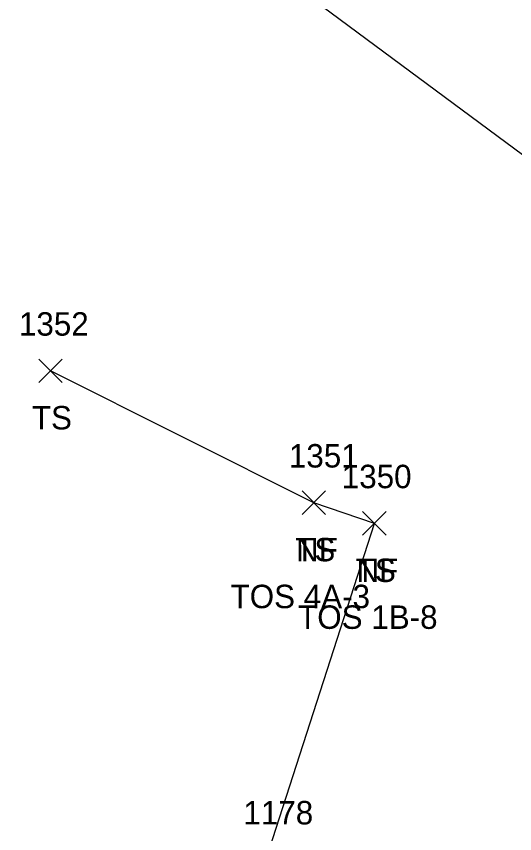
# Model space of a CAD drawing. Extents: x 1528286 to 1556263, y 492387 to 508952.
# Drawn here: x 1528641.7 to 1528684.2, y 492895.8 to 492965.5 of the extents above; entities that cross this region are included whole.
import ezdxf

# ---------------------------------------------------------------- set-up
doc = ezdxf.new("R2010")
doc.units = 0
for name, color, linetype in [('L_A', 7, 'Continuous'), ('L_C', 7, 'Continuous'), ('L_I', 7, 'Continuous'), ('L_TIC', 7, 'Continuous'), ('LELB', 7, 'Continuous')]:
    doc.layers.add(name, color=color, linetype=linetype)

msp = doc.modelspace()

# ---------------------------------------------------------------- linework, layer by layer
at = {"layer": 'L_TIC'}
for points in [[(1528643.604, 492934.296), (1528645.604, 492936.296)], [(1528645.604, 492934.296), (1528643.604, 492936.296)], [(1528643.604, 492934.296), (1528645.604, 492936.296)], [(1528645.604, 492934.296), (1528643.604, 492936.296)], [(1528666.052, 492923.046), (1528668.052, 492925.046)], [(1528668.052, 492923.046), (1528666.052, 492925.046)], [(1528666.052, 492923.046), (1528668.052, 492925.046)], [(1528668.052, 492923.046), (1528666.052, 492925.046)], [(1528666.052, 492923.046), (1528668.052, 492925.046)], [(1528668.052, 492923.046), (1528666.052, 492925.046)], [(1528666.052, 492923.046), (1528668.052, 492925.046)], [(1528668.052, 492923.046), (1528666.052, 492925.046)], [(1528671.212, 492921.281), (1528673.212, 492923.281)], [(1528673.212, 492921.281), (1528671.212, 492923.281)], [(1528671.212, 492921.281), (1528673.212, 492923.281)], [(1528673.212, 492921.281), (1528671.212, 492923.281)], [(1528671.212, 492921.281), (1528673.212, 492923.281)], [(1528673.212, 492921.281), (1528671.212, 492923.281)], [(1528671.212, 492921.281), (1528673.212, 492923.281)], [(1528673.212, 492921.281), (1528671.212, 492923.281)]]:
    msp.add_lwpolyline(points, dxfattribs=at)
at = {"layer": 'LELB'}
for points in [[(1528641.693, 492985.749), (1528687.133, 492952.057), (1528713.307, 492933.14), (1528693.777, 492897.095)], [(1528641.693, 492985.749), (1528687.133, 492952.057), (1528713.307, 492933.14), (1528693.777, 492897.095)], [(1528661.81, 492890.018), (1528672.212, 492922.281), (1528667.052, 492924.046), (1528644.604, 492935.296)], [(1528661.81, 492890.018), (1528672.212, 492922.281), (1528667.052, 492924.046), (1528644.604, 492935.296)]]:
    msp.add_lwpolyline(points, dxfattribs=at)

# ---------------------------------------------------------------- texts
at = {"layer": 'L_A'}
for s, p in [('TS', (1528643.014, 492930.296)), ('TS', (1528643.014, 492930.296)), ('TS', (1528665.462, 492919.046)), ('TS', (1528665.462, 492919.046)), ('NF', (1528665.532, 492919.046)), ('NF', (1528665.532, 492919.046)), ('TS', (1528670.622, 492917.281)), ('TS', (1528670.622, 492917.281)), ('NF', (1528670.693, 492917.281)), ('NF', (1528670.693, 492917.281))]:
    msp.add_text(s, height=2, dxfattribs=at).set_placement(p)
at = {"layer": 'L_C'}
for s, p in [('TOS 4A-3', (1528659.95, 492915.046)), ('TOS 4A-3', (1528659.95, 492915.046)), ('TOS 1B-8', (1528665.709, 492913.281)), ('TOS 1B-8', (1528665.709, 492913.281))]:
    msp.add_text(s, height=2, dxfattribs=at).set_placement(p)
at = {"layer": 'L_I'}
for s, p in [('1352', (1528641.912, 492938.296)), ('1352', (1528641.912, 492938.296)), ('1351', (1528664.926, 492927.046)), ('1351', (1528664.926, 492927.046)), ('1351', (1528664.926, 492927.046)), ('1351', (1528664.926, 492927.046)), ('1350', (1528669.433, 492925.281)), ('1350', (1528669.433, 492925.281)), ('1350', (1528669.433, 492925.281)), ('1350', (1528669.433, 492925.281)), ('1178', (1528661.048, 492896.597)), ('1178', (1528661.048, 492896.597))]:
    msp.add_text(s, height=2, dxfattribs=at).set_placement(p)

doc.saveas('drawing.dxf')
